// Mitsubishi GX Works2 project: SK2N 485-1口 MODBUS RTU 从站   PLC: FX2N/FX2NC

PROGRAM MAIN
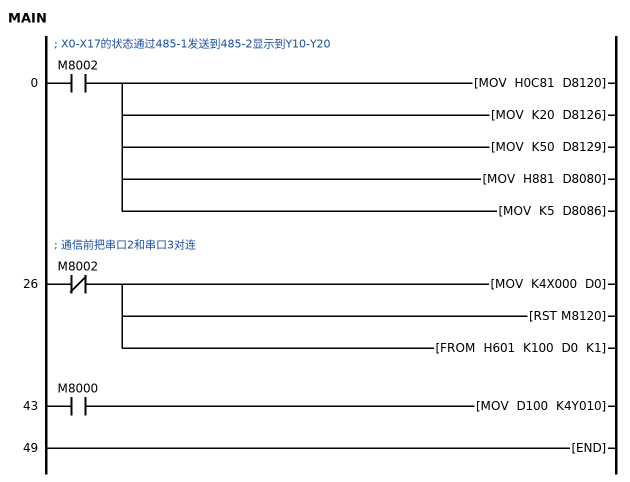
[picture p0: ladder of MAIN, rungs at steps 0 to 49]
; X0-X17的状态通过485-1发送到485-2显示到Y10-Y20
; 
0     LD      M8002
      MOV     H0C81 D8120
        [note] 485-1设置9600,N,8,1主站
      MOV     K20 D8126
        [note] 485-1发送间隔时间1=1MS  20MS
      MOV     K50 D8129
        [note] 485-1超时时间1=10MS  500MS
      MOV     H881 D8080
        [note] 485-2设置9600,N,8,1从站
      MOV     K5 D8086
        [note] 延时发送时间1=1MS  5MS
; 通信前把串口2和串口3对连
26    LDI     M8002
      MOV     K4X000 D0
        [note] X0-X17的状态存到D0
      RST     M8120
        [note] 切换到485-1口（串口2）
      FROM    H601 K100 D0 K1
        [note] 从串口2发送到串口3
43    LD      M8000
      MOV     D100 K4Y010
        [note] 收到的数据显示在Y口
49    END
END_PROGRAM
